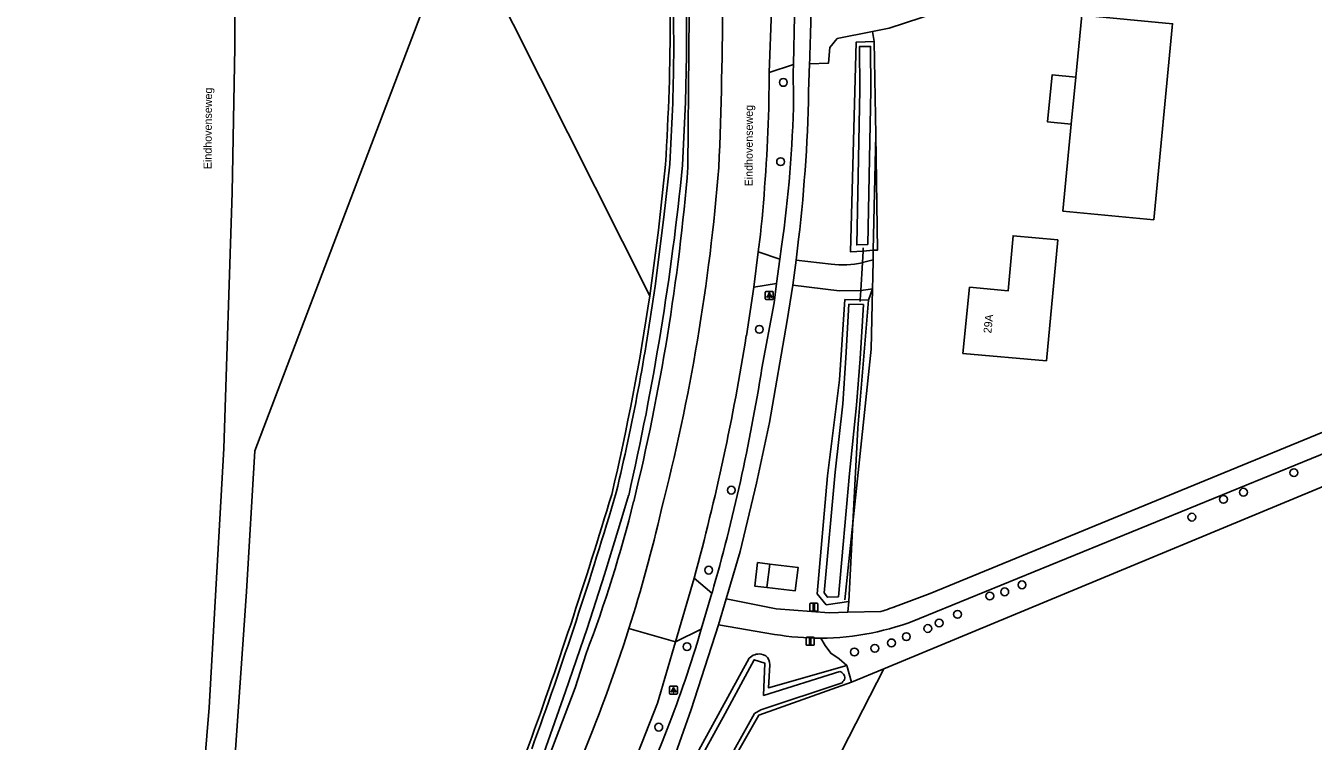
# Model space of a CAD drawing. Extents: x 162515 to 163909, y 388494 to 389773.
# Drawn here: x 162566.5 to 162727.4, y 389502.9 to 389592.3 of the extents above; entities that cross this region are included whole.
import ezdxf

# ---------------------------------------------------------------- set-up
doc = ezdxf.new("R2010")
doc.units = 0
for name, color, linetype in [('IMGEO_Afsluitpaal', 7, 'Continuous'), ('IMGEO_Berm_groen', 7, 'Continuous'), ('IMGEO_Boom', 7, 'Continuous'), ('IMGEO_Duiker', 7, 'Continuous'), ('IMGEO_Erf', 7, 'Continuous'), ('IMGEO_Fietspad_gesloten', 7, 'Continuous'), ('IMGEO_Grasland_overig', 7, 'Continuous'), ('IMGEO_Groenvoorziening', 7, 'Continuous'), ('IMGEO_Hek', 7, 'Continuous'), ('IMGEO_Lage_trafo', 7, 'Continuous'), ('IMGEO_Lichtpunt', 7, 'Continuous'), ('IMGEO_Loofbos', 7, 'Continuous'), ('IMGEO_Openbare_ruimte_label', 7, 'Continuous'), ('IMGEO_Pand', 7, 'Continuous'), ('IMGEO_Pand_nummerreeks', 7, 'Continuous'), ('IMGEO_Rijbaan_lokaal_gesloten', 7, 'Continuous'), ('IMGEO_Rijbaan_lokaal_onverhard', 7, 'Continuous'), ('IMGEO_Rijbaan_lokaal_open', 7, 'Continuous'), ('IMGEO_Rijbaan_regionaal_gesloten', 7, 'Continuous'), ('IMGEO_Voetpad_open', 7, 'Continuous'), ('IMGEO_Waterloop', 7, 'Continuous')]:
    doc.layers.add(name, color=color, linetype=linetype)

msp = doc.modelspace()

# ---------------------------------------------------------------- linework, layer by layer
at = {"layer": 'IMGEO_Afsluitpaal'}
for p, q in [((162664.5, 389519.22), (162664.5, 389520.02)), ((162664.5, 389520.02), (162664.5, 389519.22)), ((162664.6, 389520.12), (162665.39, 389520.12)), ((162665.39, 389520.12), (162664.6, 389520.12)), ((162665.39, 389519.12), (162664.6, 389519.12)), ((162664.6, 389519.12), (162665.39, 389519.12)), ((162665.49, 389520.02), (162665.49, 389519.22)), ((162665.49, 389519.22), (162665.49, 389520.02)), ((162664.05, 389514.97), (162664.05, 389515.77)), ((162664.05, 389515.77), (162664.05, 389514.97)), ((162664.15, 389515.87), (162664.94, 389515.87)), ((162664.94, 389515.87), (162664.15, 389515.87)), ((162665.04, 389515.77), (162665.04, 389514.97)), ((162665.04, 389514.97), (162665.04, 389515.77)), ((162664.94, 389514.87), (162664.15, 389514.87)), ((162664.15, 389514.87), (162664.94, 389514.87))]:
    msp.add_line(p, q, dxfattribs=at)
for points in [[(162664.92, 389519.99), (162665.07, 389519.99), (162665.07, 389519.24), (162664.92, 389519.24), (162664.92, 389519.99)], [(162664.47, 389515.74), (162664.62, 389515.74), (162664.62, 389514.99), (162664.47, 389514.99), (162664.47, 389515.74)]]:
    msp.add_lwpolyline(points, dxfattribs=at)
for centre, start, end in [((162664.6, 389520.02), 90, 180), ((162664.6, 389520.02), 90, 180), ((162664.6, 389519.22), 180, 270), ((162664.6, 389519.22), 180, 270), ((162665.39, 389520.02), 0, 90), ((162665.39, 389520.02), 360, 90), ((162665.39, 389519.22), 270, 0), ((162665.39, 389519.22), 270, 0), ((162664.15, 389515.77), 90, 180), ((162664.15, 389515.77), 90, 180), ((162664.94, 389515.77), 0, 90), ((162664.94, 389515.77), 360, 90), ((162664.15, 389514.97), 180, 270), ((162664.15, 389514.97), 180, 270), ((162664.94, 389514.97), 270, 0), ((162664.94, 389514.97), 270, 0)]:
    msp.add_arc(centre, 0.1, start, end, dxfattribs=at)
at = {"layer": 'IMGEO_Berm_groen'}
for points in [[(162644.49, 389558.55), (162620.58, 389606.08), (162595.14, 389539.18), (162594.1, 389521.6), (162592.59, 389500), (162590.76, 389474.27), (162589.21, 389455.96), (162585.24, 389425.59), (162584.14, 389417.99), (162582.08, 389406.23), (162581.11, 389399), (162577.41, 389384.02), (162585.92, 389402.74)], [(162649.26, 389574.61), (162649.5, 389603.47)], [(162646.45, 389574.95), (162645.59, 389566.74), (162644.49, 389558.55)], [(162585.92, 389402.74), (162591.02, 389416.77), (162596.97, 389430.04), (162609.1, 389453.15), (162626.82, 389489.12), (162628.85, 389493.53), (162631.52, 389500), (162635.15, 389509.54), (162636.54, 389513.85)]]:
    msp.add_lwpolyline(points, dxfattribs=at)
for centre, radius, start, end in [((162355.99, 389593.66), 291.06, 356.3143, 359.9944), ((162382.24, 389596.53), 267.92, 346.248, 355.3073), ((162484.49, 389571.75), 162.7, 339.1515, 346.1624)]:
    msp.add_arc(centre, radius, start, end, dxfattribs=at)
at = {"layer": 'IMGEO_Boom'}
for centre in [(162661.18, 389585.2), (162660.84, 389575.29), (162658.18, 389554.34), (162725, 389536.43), (162654.68, 389534.25), (162716.2, 389533.1), (162718.7, 389533.99), (162712.25, 389530.88), (162651.85, 389524.26), (162688.86, 389521.54), (162691.02, 389522.42), (162686.99, 389521.03), (162682.96, 389518.73), (162679.24, 389516.96), (162680.66, 389517.65), (162674.7, 389515.16), (162676.56, 389515.95), (162649.14, 389514.69), (162670.07, 389514.03), (162672.62, 389514.49), (162645.61, 389504.64)]:
    msp.add_circle(centre, 0.489, dxfattribs=at)
at = {"layer": 'IMGEO_Duiker'}
msp.add_lwpolyline([(162670.77, 389557.84), (162670.79, 389558.03), (162670.86, 389559.19), (162671.07, 389562.68), (162671.15, 389564.12), (162671.18, 389564.55)], dxfattribs=at)
at = {"layer": 'IMGEO_Erf'}
for points in [[(162672.54, 389590.33), (162672.73, 389578.64), (162672.97, 389564.25), (162672.43, 389564.22)], [(162669.89, 389530.14), (162669.39, 389520.32)]]:
    msp.add_lwpolyline(points, dxfattribs=at)
at = {"layer": 'IMGEO_Fietspad_gesloten'}
for points in [[(162662.44, 389587.44), (162662.4, 389586.52), (162662.46, 389583.17)], [(162664.36, 389585.24), (162664.46, 389587.51)], [(162662.78, 389563), (162663.09, 389565.61)], [(162660.97, 389564.69), (162660.76, 389563.12)], [(162654.04, 389520.66), (162655.77, 389526.57), (162657.82, 389535.12), (162659.45, 389542.7), (162661.68, 389555.43), (162662.38, 389559.85)], [(162660.35, 389560.06), (162660.02, 389557.64), (162658.49, 389549.48)], [(162647.23, 389500), (162649.65, 389506.83), (162653.09, 389517.43)], [(162650.92, 389516.86), (162650.41, 389515.13)], [(162646.06, 389502.88), (162644.92, 389500)]]:
    msp.add_lwpolyline(points, dxfattribs=at)
for centre, radius, start, end in [((162480.12, 389587.33), 184.25, 353.2323, 359.3501), ((162510.28, 389586.14), 152.21, 351.9014, 358.8829), ((162424.96, 389586.53), 236.46, 344.0067, 350.9858), ((162501.6, 389561.09), 155.75, 338.0505, 342.8369)]:
    msp.add_arc(centre, radius, start, end, dxfattribs=at)
at = {"layer": 'IMGEO_Grasland_overig'}
for points in [[(162669.89, 389530.14), (162672.17, 389551.86), (162672.33, 389559.41)], [(162671.83, 389558.01), (162672.33, 389559.41)], [(162671.83, 389558.01), (162670.49, 389542.01), (162669.89, 389530.14)], [(162673.74, 389511.91), (162660.64, 389486.29), (162645.79, 389460.14), (162630.34, 389430.94), (162620.12, 389411.44), (162611.16, 389387.65), (162603.73, 389364.73), (162600.09, 389349.34), (162595.22, 389323.12), (162589.65, 389295.27), (162587.18, 389279.33), (162585.38, 389264.9)], [(162600.27, 389394.52), (162602.54, 389399.82), (162606.39, 389409.53), (162610.2, 389417.85), (162613.42, 389423.52), (162634.26, 389464.15), (162635.68, 389466.73), (162638.44, 389471.71), (162643.96, 389481.23), (162654.64, 389500), (162658.13, 389506.14), (162669.72, 389510.24)]]:
    msp.add_lwpolyline(points, dxfattribs=at)
at = {"layer": 'IMGEO_Groenvoorziening'}
for points in [[(162672.34, 389591.57), (162672.54, 389590.33)], [(162672.54, 389590.33), (162670.3, 389590.24), (162669.58, 389564.01), (162671.15, 389564.12), (162672.43, 389564.22)], [(162672.43, 389564.22), (162672.4, 389563.04)], [(162669.39, 389520.32), (162666.55, 389519.93), (162665.43, 389521.3), (162666.7, 389536.03), (162668.21, 389548.03), (162668.88, 389558.07), (162670.79, 389558.03), (162671.83, 389558.01)], [(162669.24, 389518.99), (162669.39, 389520.32)], [(162656.93, 389513.26), (162649.65, 389500), (162648.65, 389498.18), (162641.58, 389481.68), (162627.11, 389453.02), (162612.64, 389424.36), (162609.62, 389419.27), (162606.43, 389411.88), (162603.24, 389404.49), (162601.6, 389400.16), (162599.96, 389395.82), (162599.12, 389393.9), (162598.29, 389391.98), (162596.4, 389386.5), (162594.6, 389381.31), (162594.5, 389381.03), (162590.13, 389365.03)], [(162669.13, 389512.35), (162659.31, 389509.55), (162659.49, 389512.43), (162659.45, 389512.76), (162659.37, 389513.06)]]:
    msp.add_lwpolyline(points, dxfattribs=at)
for centre, radius, start, end in [((162658.17, 389512.05), 1.73, 82.1874, 135.6818), ((162658.33, 389512.65), 1.11, 21.5639, 86.0838)]:
    msp.add_arc(centre, radius, start, end, dxfattribs=at)
at = {"layer": 'IMGEO_Hek'}
for points in [[(162672.73, 389578.64), (162672.43, 389564.22)], [(162672.4, 389563.04), (162672.43, 389564.22)], [(162672.36, 389560.9), (162672.4, 389563.04)], [(162672.36, 389560.9), (162672.33, 389559.41)], [(162672.33, 389559.41), (162672.17, 389551.86), (162669.89, 389530.14)], [(162669.89, 389530.14), (162668.88, 389520.54)]]:
    msp.add_lwpolyline(points, dxfattribs=at)
at = {"layer": 'IMGEO_Lage_trafo'}
for points in [[(162659.49, 389525.02), (162659.14, 389522.08)], [(162659.49, 389525.02), (162663.02, 389524.6), (162662.66, 389521.66), (162659.14, 389522.08)]]:
    msp.add_lwpolyline(points, dxfattribs=at)
at = {"layer": 'IMGEO_Lichtpunt'}
for p, q in [((162658.93, 389558.98), (162658.93, 389558.17)), ((162658.93, 389558.98), (162658.93, 389558.17)), ((162659.83, 389559.08), (162659.03, 389559.08)), ((162659.83, 389559.08), (162659.03, 389559.08)), ((162659.93, 389558.17), (162659.93, 389558.98)), ((162659.93, 389558.17), (162659.93, 389558.98)), ((162659.03, 389558.08), (162659.83, 389558.08)), ((162659.03, 389558.08), (162659.83, 389558.08)), ((162646.96, 389509.65), (162646.96, 389508.85)), ((162646.96, 389509.65), (162646.96, 389508.85)), ((162647.86, 389509.75), (162647.05, 389509.75)), ((162647.86, 389509.75), (162647.05, 389509.75)), ((162647.96, 389508.85), (162647.96, 389509.65)), ((162647.96, 389508.85), (162647.96, 389509.65)), ((162647.05, 389508.75), (162647.86, 389508.75)), ((162647.05, 389508.75), (162647.86, 389508.75))]:
    msp.add_line(p, q, dxfattribs=at)
for points in [[(162659.31, 389558.64), (162659.34, 389558.62), (162659.16, 389558.35), (162659.12, 389558.38), (162659.31, 389558.64)], [(162659.41, 389558.6), (162659.46, 389558.6), (162659.46, 389558.27), (162659.41, 389558.27), (162659.41, 389558.6)], [(162659.52, 389558.62), (162659.56, 389558.64), (162659.74, 389558.38), (162659.7, 389558.35), (162659.52, 389558.62)], [(162647.33, 389509.32), (162647.37, 389509.29), (162647.19, 389509.03), (162647.15, 389509.05), (162647.33, 389509.32)], [(162647.44, 389509.27), (162647.48, 389509.27), (162647.48, 389508.95), (162647.44, 389508.95), (162647.44, 389509.27)], [(162647.55, 389509.29), (162647.58, 389509.32), (162647.77, 389509.05), (162647.73, 389509.03), (162647.55, 389509.29)]]:
    msp.add_lwpolyline(points, dxfattribs=at)
for centre in [(162659.43, 389558.78), (162647.46, 389509.45)]:
    msp.add_circle(centre, 0.0994, dxfattribs=at)
for centre, start, end in [((162659.03, 389558.98), 90, 180), ((162659.03, 389558.98), 90, 180), ((162659.83, 389558.98), 0, 90), ((162659.83, 389558.98), 0, 90), ((162659.03, 389558.17), 180, 270), ((162659.03, 389558.17), 180, 270), ((162659.83, 389558.17), 270, 0), ((162659.83, 389558.17), 270, 360), ((162647.05, 389509.65), 90, 180), ((162647.05, 389509.65), 90, 180), ((162647.86, 389509.65), 0, 90), ((162647.86, 389509.65), 0, 90), ((162647.05, 389508.85), 180, 270), ((162647.05, 389508.85), 180, 270), ((162647.86, 389508.85), 270, 0), ((162647.86, 389508.85), 270, 360)]:
    msp.add_arc(centre, 0.0946, start, end, dxfattribs=at)
at = {"layer": 'IMGEO_Loofbos'}
for points in [[(162747.64, 389542.57), (162673.74, 389511.91)], [(162669.13, 389512.35), (162668.18, 389513.17), (162667.11, 389513.87), (162666.43, 389514.84), (162665.88, 389515.76)], [(162669.72, 389510.24), (162669.13, 389512.35)], [(162673.74, 389511.91), (162669.72, 389510.24)]]:
    msp.add_lwpolyline(points, dxfattribs=at)
for centre, radius, start, end in [((162350.46, 389602.03), 297.23, 346.7142, 351.5887), ((162054.39, 389709.72), 611.23, 340.07097, 343.26545)]:
    msp.add_arc(centre, radius, start, end, dxfattribs=at)
at = {"layer": 'IMGEO_Pand'}
for points in [[(162697.73, 389585.85), (162698.48, 389593.62), (162709.84, 389592.54), (162709.8, 389592.12), (162707.49, 389568.04), (162696.13, 389569.12), (162697.17, 389579.98)], [(162697.17, 389579.98), (162694.21, 389580.26), (162694.77, 389586.13), (162697.73, 389585.85)], [(162697.17, 389579.98), (162697.73, 389585.85)], [(162694.09, 389550.39), (162683.64, 389551.34), (162684.47, 389559.61), (162689.28, 389559.14), (162689.91, 389566.03), (162695.48, 389565.52), (162694.09, 389550.39)]]:
    msp.add_lwpolyline(points, dxfattribs=at)
at = {"layer": 'IMGEO_Rijbaan_lokaal_gesloten'}
for points in [[(162659.43, 389586.46), (162659.7, 389594.2), (162659.7, 389594.37)], [(162659.36, 389581.96), (162659.43, 389586.46)], [(162658.05, 389564.02), (162658.33, 389566.21)], [(162657.51, 389559.61), (162658.05, 389564.02)], [(162656.56, 389553.55), (162657.51, 389559.61)], [(162647.7, 389515.28), (162650.04, 389523.27)], [(162641.88, 389516.97), (162647.7, 389515.28)], [(162600.02, 389411.37), (162627.43, 389468.36), (162636.47, 389486.06), (162642.44, 389500), (162645.44, 389507.62), (162647.7, 389515.28)]]:
    msp.add_lwpolyline(points, dxfattribs=at)
for centre, radius, start, end in [((162147.36, 389596.48), 506.23, 357.5204, 0.0055), ((162435.85, 389588.67), 223.61, 354.2359, 358.2813), ((162403.45, 389594.56), 250.47, 345.4722, 355.4263), ((162373.2, 389598.7), 286.93, 344.7591, 350.948), ((162457.04, 389575.4), 193.86, 342.4581, 346.9798), ((162457.46, 389575.29), 193.42, 337.0928, 342.4522)]:
    msp.add_arc(centre, radius, start, end, dxfattribs=at)
at = {"layer": 'IMGEO_Rijbaan_lokaal_onverhard'}
for points in [[(162675.54, 389519.85), (162679.52, 389521.34), (162765.33, 389556.56), (162788.12, 389565.57), (162797.51, 389568.67), (162797.54, 389568.68)], [(162678.22, 389518.21), (162749.68, 389547.35)], [(162653.09, 389517.43), (162654.04, 389520.66)], [(162654.04, 389520.66), (162659.44, 389519.57), (162660.29, 389519.4), (162666.92, 389518.94), (162669.24, 389518.99)], [(162669.24, 389518.99), (162673.37, 389519.09)], [(162653.09, 389517.43), (162660.1, 389516.23)]]:
    msp.add_lwpolyline(points, dxfattribs=at)
for centre, radius, start, end in [((162664.75, 389547.12), 29.33, 287.0922, 291.5774), ((162665.69, 389549.04), 33.28, 270.3292, 292.1192), ((162665.71, 389549.24), 33.48, 260.3528, 270.2938)]:
    msp.add_arc(centre, radius, start, end, dxfattribs=at)
at = {"layer": 'IMGEO_Rijbaan_lokaal_open'}
for points in [[(162705.55, 389603.52), (162699.99, 389600.99), (162689.36, 389596.71), (162682.45, 389594.59), (162674.43, 389591.99), (162672.34, 389591.57)], [(162662.6, 389593.5), (162662.44, 389587.44)], [(162664.46, 389587.51), (162666.83, 389587.61), (162666.99, 389589.58), (162667.93, 389590.68), (162672.34, 389591.57)], [(162662.44, 389587.44), (162659.43, 389586.46)], [(162658.05, 389564.02), (162660.76, 389563.12)], [(162660.76, 389563.12), (162660.35, 389560.06)], [(162662.38, 389559.85), (162662.78, 389563)], [(162667.15, 389562.49), (162662.78, 389563)], [(162672.4, 389563.04), (162671.07, 389562.68)], [(162672.4, 389563.04), (162672.36, 389560.9), (162672.33, 389559.41)], [(162660.35, 389560.06), (162657.51, 389559.61)], [(162672.33, 389559.41), (162672.08, 389559.37), (162670.86, 389559.19), (162668.16, 389559.16), (162662.38, 389559.85)], [(162650.04, 389523.27), (162652.26, 389521.38)], [(162652.26, 389521.38), (162650.92, 389516.86)], [(162650.92, 389516.86), (162647.7, 389515.28)]]:
    msp.add_lwpolyline(points, dxfattribs=at)
for centre, radius, start, end in [((162443.38, 389596.31), 221.26, 357.7187, 0.5807), ((162668.54, 389574.59), 12.18, 263.413, 281.9618)]:
    msp.add_arc(centre, radius, start, end, dxfattribs=at)
at = {"layer": 'IMGEO_Rijbaan_regionaal_gesloten'}
msp.add_lwpolyline([(162566.49, 389328.54), (162573.3, 389367.99), (162577.24, 389393.15), (162579.8, 389412.03), (162581.3, 389425.76), (162583.5, 389442.96), (162584.99, 389456.28), (162587.36, 389481.75), (162588.85, 389500), (162589.4, 389507.11), (162591.26, 389539.46), (162592.3, 389571.45), (162592.61, 389589.61), (162592.64, 389612.42)], dxfattribs=at)
at = {"layer": 'IMGEO_Voetpad_open'}
msp.add_lwpolyline([(162659.14, 389522.08), (162657.63, 389522.25), (162657.97, 389525.21), (162659.49, 389525.02)], dxfattribs=at)
at = {"layer": 'IMGEO_Waterloop'}
for points in [[(162647.48, 389588.56), (162647.43, 389598.95), (162647.36, 389605.49), (162647.06, 389613.33), (162646.47, 389621.53), (162648.07, 389621.74)], [(162648.97, 389605.53), (162649.04, 389598.97), (162649.09, 389588.55), (162648.97, 389582.74), (162648.59, 389574.86)], [(162671.74, 389564.94), (162670.36, 389564.9), (162670.74, 389584.27), (162670.71, 389589.7), (162672.09, 389589.7), (162672.11, 389584.25), (162671.74, 389564.94)], [(162645.15, 389559.73), (162646.23, 389568.36), (162646.99, 389574.99)], [(162669.39, 389557.49), (162671.2, 389557.43), (162670.8, 389550.67), (162670.35, 389544.88), (162669.47, 389536.32), (162668.06, 389520.93), (162666.7, 389520.86), (162666.29, 389521.42), (162667.67, 389536.5), (162668.63, 389545.03), (162668.99, 389550.78), (162669.39, 389557.49)], [(162641.85, 389533.57), (162641.01, 389530.78), (162638.84, 389523.7), (162636.65, 389516.97), (162633.95, 389509.11), (162631.24, 389501.38), (162630.27, 389499.03), (162628.95, 389496.02), (162627.2, 389491.88), (162625.71, 389488.68), (162624.4, 389486.02), (162622, 389481.02), (162618.27, 389473.47), (162615.2, 389467.11), (162611.94, 389460.37), (162608.55, 389453.55), (162604.49, 389445.66), (162600.28, 389437.47), (162596.98, 389431.12), (162595.52, 389427.71), (162591.96, 389419.68), (162589.94, 389414.8), (162586.55, 389405.61), (162585.04, 389406.17)], [(162649.25, 389497.84), (162653.92, 389506.36), (162657.55, 389513.06), (162658.86, 389512.64), (162658.71, 389508.6), (162668.26, 389511.6)], [(162668.7, 389511.26), (162668.83, 389511.05)], [(162668.74, 389510.45), (162668.64, 389510.32), (162668.52, 389510.19), (162658.39, 389506.79), (162657.56, 389506.34), (162643.33, 389480.86), (162640.01, 389475.18), (162633.79, 389463.77), (162631.71, 389459.71), (162629.67, 389455.81), (162626.03, 389448.62), (162622.32, 389441.29), (162613.52, 389424.14), (162610.05, 389417.95), (162607.54, 389412.57), (162604.25, 389404.96), (162602.24, 389399.81), (162600.33, 389394.95), (162599.78, 389393.77), (162599.09, 389391.64), (162596.85, 389385.15), (162595.48, 389380.91), (162593.29, 389373.25), (162591.12, 389365.3)]]:
    msp.add_lwpolyline(points, dxfattribs=at)
for centre, radius, start, end in [((162399.35, 389590.8), 248.14, 356.3473, 359.4839), ((162311.66, 389608.68), 338.63, 347.184, 354.2682), ((162376.01, 389597.19), 271.74, 346.5466, 352.0744), ((162123.35, 389686.64), 539.02, 339.9616, 343.5467), ((162667.62, 389510.31), 1.44, 41.5659, 63.8729), ((162668.28, 389510.83), 0.589, 320.7884, 22.1971)]:
    msp.add_arc(centre, radius, start, end, dxfattribs=at)

# ---------------------------------------------------------------- texts
at = {"layer": 'IMGEO_Openbare_ruimte_label'}
for rotation, p in [(89.5989, (162589.71, 389574.36)), (89.8281, (162657.35, 389572.21))]:
    msp.add_text('Eindhovenseweg', height=1, rotation=rotation, dxfattribs=at).set_placement(p)
at = {"layer": 'IMGEO_Pand_nummerreeks'}
msp.add_text('29A', height=1, rotation=84.3114, dxfattribs=at).set_placement((162687.18, 389553.8))

doc.saveas('drawing.dxf')
